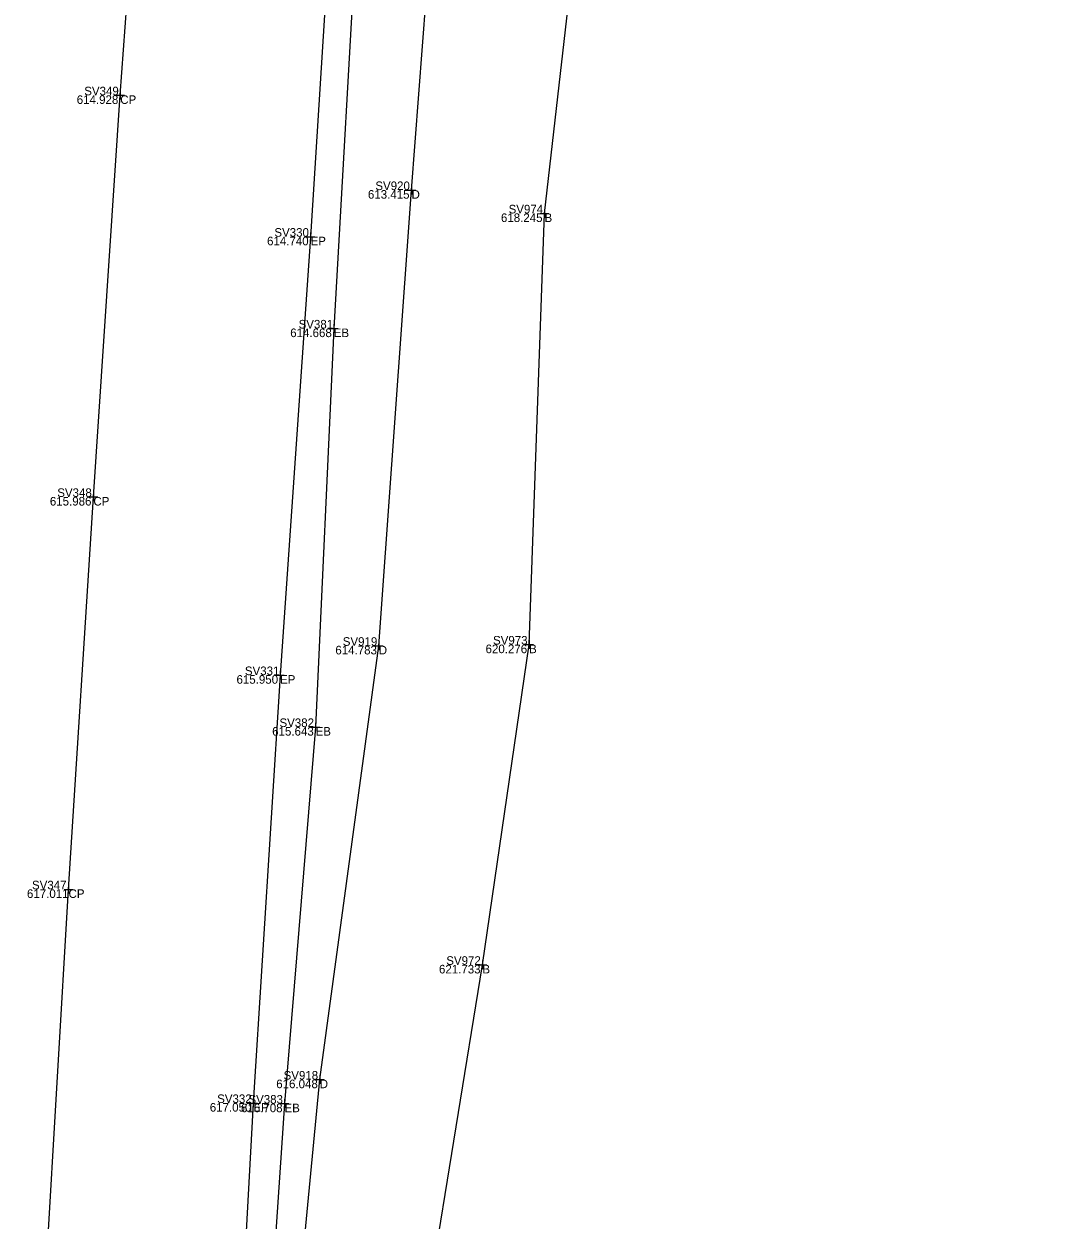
# Model space of a CAD drawing. Extents: x -2 to 1979875, y -2 to 232027.
# Drawn here: x 1978747.9 to 1978807.2, y 230841.9 to 230911.4 of the extents above; entities that cross this region are included whole.
import ezdxf

# ---------------------------------------------------------------- set-up
doc = ezdxf.new("R2010")
doc.units = 0
for name, color, linetype in [('_CIVIL_CONSTRUCTION', 7, 'Continuous'), ('DR_X_Ditch', 7, 'Continuous'), ('GE_P_Alignment', 7, 'Continuous'), ('GE_X_Alignment', 7, 'Continuous'), ('GE_X_Alignment_1000_Curve_Data', 7, 'Continuous'), ('GE_X_Alignment_1000_Stations', 7, 'Continuous'), ('GE_X_Alignment_100_Curve_Data', 7, 'Continuous'), ('GE_X_Alignment_100_Stations', 7, 'Continuous'), ('SC_Scratch1', 7, 'Continuous')]:
    doc.layers.add(name, color=color, linetype=linetype)

msp = doc.modelspace()

# ---------------------------------------------------------------- linework, layer by layer
at = {"layer": 'DR_X_Ditch'}
msp.add_lwpolyline([(1978769.61, 230735.533), (1978764.556, 230757.762), (1978761.888, 230780.52), (1978761.255, 230802.491), (1978762.758, 230825.129), (1978765.137, 230850.029), (1978768.569, 230875.252), (1978770.473, 230901.75), (1978772.394, 230926.88), (1978774.225, 230946.118), (1978776.188, 230970.1), (1978776.947, 230991.277), (1978778.808, 231013.722), (1978780.679, 231036.008), (1978780.852, 231047.689), (1978785.42, 231078.945), (1978790.697, 231097.051), (1978792.307, 231119.545), (1978794.395, 231141.248), (1978795.023, 231162.503), (1978796.552, 231185.182), (1978801.304, 231199.708)], dxfattribs=at)
at = {"layer": 'GE_P_Alignment'}
msp.add_lwpolyline([(1978769.951, 230803.3), (1978770.804, 230818.73), (1978769.172, 230825.121), (1978771.54, 230837.858), (1978774.593, 230856.702), (1978777.309, 230875.323), (1978778.206, 230900.393), (1978780.194, 230917.861), (1978782.495, 230932.89), (1978782.493, 230947.115), (1978785.767, 230964.209), (1978787.856, 230986.866), (1978787.326, 231009.356), (1978787.324, 231025.342), (1978791.304, 231037.316), (1978793.971, 231062.015), (1978792.008, 231077.675), (1978794.496, 231103.739), (1978796.727, 231125.192), (1978800.775, 231143.28), (1978803.614, 231161.931), (1978803.663, 231181.675), (1978807.191, 231198.311), (1978806.504, 231203.464)], dxfattribs=at)
at = {"layer": 'GE_X_Alignment_1000_Curve_Data'}
msp.add_lwpolyline([(1978771.368, 230686.901), (1978762.945, 230707.808), (1978756.184, 230729.845), (1978751.49, 230752.309), (1978748.994, 230772.916), (1978748.08, 230796.049), (1978747.937, 230796.247), (1978748.471, 230819.071), (1978749.254, 230839.296), (1978750.532, 230861.092), (1978751.977, 230883.907), (1978753.538, 230907.259), (1978755.272, 230931.005), (1978756.708, 230952.708), (1978758.182, 230974.871), (1978759.598, 230998.872), (1978761.121, 231023.464)], dxfattribs=at)
at = {"layer": 'GE_X_Alignment_1000_Stations'}
msp.add_lwpolyline([(1978785.568, 231251.827), (1978784.19, 231242.096), (1978782.784, 231222.648), (1978782.32, 231202.663), (1978780.702, 231177.057), (1978778.946, 231150.803), (1978777.805, 231126.797), (1978776.986, 231106.931), (1978775.705, 231085.257), (1978774.572, 231063.753), (1978773.517, 231041.76), (1978772.029, 231016.51), (1978770.7, 230994.507), (1978769.257, 230972.092), (1978767.73, 230948.595), (1978766.192, 230924.232), (1978764.603, 230899.039), (1978762.827, 230873.547), (1978761.273, 230848.668), (1978759.848, 230822.744), (1978759.345, 230799.915), (1978760.114, 230777.862), (1978762.938, 230755.551), (1978769.839, 230729.514)], dxfattribs=at)
at = {"layer": 'GE_X_Alignment_100_Curve_Data'}
for p, q in [((1978753.538, 230907.509), (1978753.538, 230907.009)), ((1978753.288, 230907.259), (1978753.788, 230907.259)), ((1978753.538, 230907.259), (1978753.538, 230907.259)), ((1978770.473, 230902), (1978770.473, 230901.5)), ((1978770.223, 230901.75), (1978770.723, 230901.75)), ((1978770.473, 230901.75), (1978770.473, 230901.75)), ((1978778.206, 230900.643), (1978778.206, 230900.143)), ((1978777.956, 230900.393), (1978778.456, 230900.393)), ((1978778.206, 230900.393), (1978778.206, 230900.393)), ((1978764.603, 230899.289), (1978764.603, 230898.789)), ((1978764.353, 230899.039), (1978764.853, 230899.039)), ((1978764.603, 230899.039), (1978764.603, 230899.039)), ((1978765.7, 230893.701), (1978766.2, 230893.701)), ((1978765.95, 230893.951), (1978765.95, 230893.451)), ((1978765.95, 230893.701), (1978765.95, 230893.701)), ((1978751.727, 230883.907), (1978752.227, 230883.907)), ((1978751.977, 230884.157), (1978751.977, 230883.657)), ((1978751.977, 230883.907), (1978751.977, 230883.907)), ((1978768.569, 230875.502), (1978768.569, 230875.002)), ((1978777.309, 230875.573), (1978777.309, 230875.073)), ((1978768.319, 230875.252), (1978768.819, 230875.252)), ((1978768.569, 230875.252), (1978768.569, 230875.252)), ((1978777.059, 230875.323), (1978777.559, 230875.323)), ((1978777.309, 230875.323), (1978777.309, 230875.323)), ((1978762.577, 230873.547), (1978763.077, 230873.547)), ((1978762.827, 230873.797), (1978762.827, 230873.297)), ((1978762.827, 230873.547), (1978762.827, 230873.547)), ((1978764.896, 230870.78), (1978764.896, 230870.28)), ((1978764.646, 230870.53), (1978765.146, 230870.53)), ((1978764.896, 230870.53), (1978764.896, 230870.53)), ((1978750.282, 230861.092), (1978750.782, 230861.092)), ((1978750.532, 230861.342), (1978750.532, 230860.842)), ((1978750.532, 230861.092), (1978750.532, 230861.092)), ((1978774.343, 230856.702), (1978774.843, 230856.702)), ((1978774.593, 230856.952), (1978774.593, 230856.452)), ((1978774.593, 230856.702), (1978774.593, 230856.702)), ((1978764.887, 230850.029), (1978765.387, 230850.029)), ((1978765.137, 230850.279), (1978765.137, 230849.779)), ((1978765.137, 230850.029), (1978765.137, 230850.029)), ((1978761.023, 230848.668), (1978761.523, 230848.668)), ((1978761.273, 230848.918), (1978761.273, 230848.418)), ((1978761.273, 230848.668), (1978761.273, 230848.668)), ((1978762.838, 230848.633), (1978763.338, 230848.633)), ((1978763.088, 230848.883), (1978763.088, 230848.383)), ((1978763.088, 230848.633), (1978763.088, 230848.633))]:
    msp.add_line(p, q, dxfattribs=at)
at = {"layer": 'SC_Scratch1'}
msp.add_lwpolyline([(1978787.694, 231249.601), (1978785.48, 231226.833), (1978784.558, 231206.407), (1978783.016, 231187.193), (1978782.112, 231167.584), (1978780.51, 231145.937), (1978779.287, 231125.907), (1978778.425, 231108.773), (1978777.775, 231087.524), (1978776.748, 231064.782), (1978775.35, 231040.582), (1978774.462, 231016.281), (1978772.549, 230990.683), (1978771.051, 230965.635), (1978769.086, 230942.407), (1978767.324, 230917.989), (1978765.95, 230893.701), (1978764.896, 230870.53), (1978763.088, 230848.633), (1978761.583, 230826.273), (1978760.498, 230804.271), (1978761.5, 230780.247), (1978763.845, 230755.469), (1978770.352, 230731.454)], dxfattribs=at)

# ---------------------------------------------------------------- texts
at = {"layer": '_CIVIL_CONSTRUCTION'}
for s, p in [('614.928', (1978751.008, 230906.759)), ('613.415', (1978767.938, 230901.25)), ('618.245', (1978775.671, 230899.893)), ('614.740', (1978762.073, 230898.539)), ('614.668', (1978763.42, 230893.201)), ('615.986', (1978749.445, 230883.407)), ('614.783', (1978766.044, 230874.752)), ('620.276', (1978774.777, 230874.823)), ('615.950', (1978760.297, 230873.047)), ('615.643', (1978762.371, 230870.03)), ('617.011', (1978748.114, 230860.592)), ('621.733', (1978772.068, 230856.202)), ('616.048', (1978762.607, 230849.529)), ('617.050', (1978758.743, 230848.168)), ('616.708', (1978760.558, 230848.133))]:
    msp.add_text(s, height=0.5, dxfattribs=at).set_placement(p)
at = {"layer": 'GE_X_Alignment'}
for s, p in [('SV349', (1978751.444, 230907.259)), ('SV920', (1978768.369, 230901.75)), ('SV974', (1978776.117, 230900.393)), ('SV330', (1978762.499, 230899.039)), ('SV381', (1978763.907, 230893.701)), ('SV348', (1978749.874, 230883.907)), ('SV919', (1978766.475, 230875.252)), ('SV973', (1978775.211, 230875.323)), ('SV331', (1978760.784, 230873.547)), ('SV382', (1978762.795, 230870.53)), ('SV347', (1978748.407, 230861.092)), ('SV972', (1978772.492, 230856.702)), ('SV918', (1978763.034, 230850.029)), ('SV332', (1978759.172, 230848.668)), ('SV383', (1978760.99, 230848.633))]:
    msp.add_text(s, height=0.5, dxfattribs=at).set_placement(p)
at = {"layer": 'GE_X_Alignment_100_Stations'}
for s, p in [('CP', (1978753.538, 230906.759)), ('D', (1978770.473, 230901.25)), ('B', (1978778.206, 230899.893)), ('EP', (1978764.603, 230898.539)), ('EB', (1978765.95, 230893.201)), ('CP', (1978751.977, 230883.407)), ('D', (1978768.569, 230874.752)), ('B', (1978777.309, 230874.823)), ('EP', (1978762.827, 230873.047)), ('EB', (1978764.896, 230870.03)), ('CP', (1978750.532, 230860.592)), ('B', (1978774.593, 230856.202)), ('D', (1978765.137, 230849.529)), ('EP', (1978761.273, 230848.168)), ('EB', (1978763.088, 230848.133))]:
    msp.add_text(s, height=0.5, dxfattribs=at).set_placement(p)

doc.saveas('drawing.dxf')
